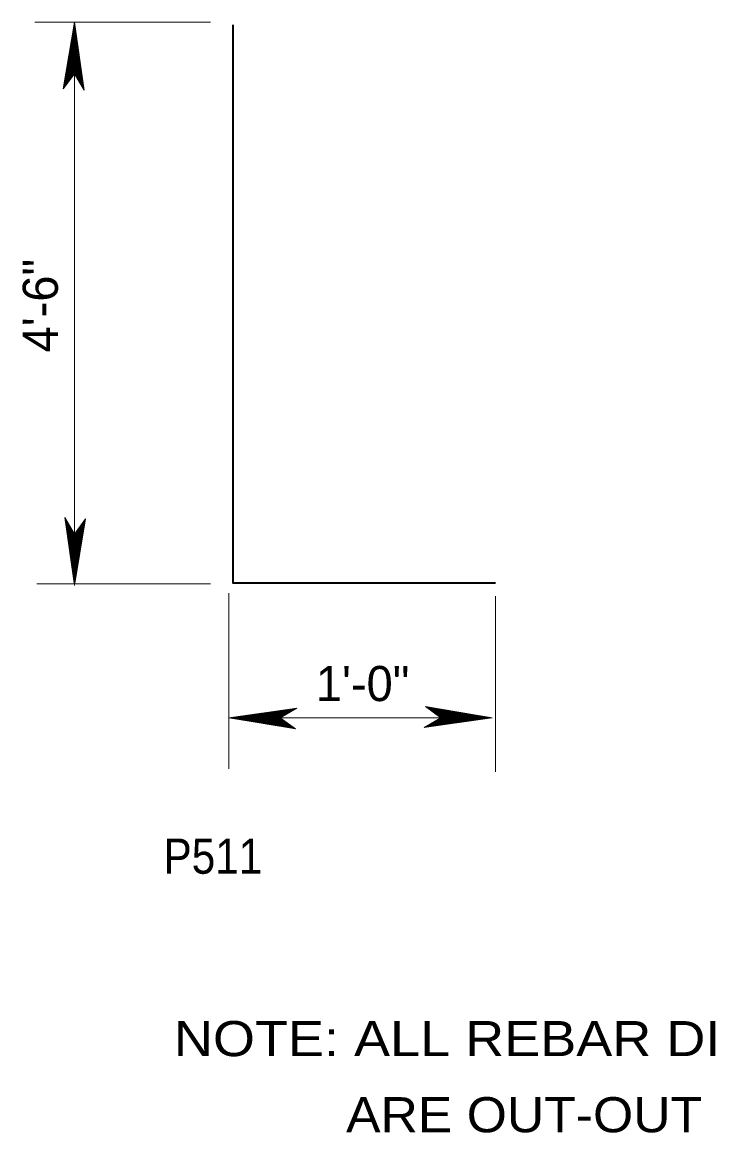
# Model space of a CAD drawing. Extents: x 144 to 252, y 360 to 425.
# Drawn here: x 210.54 to 216.11, y 380.2 to 389.15 of the extents above; entities that cross this region are included whole.
import ezdxf

# ---------------------------------------------------------------- set-up
doc = ezdxf.new("R2010")
doc.units = 0
doc.header["$LTSCALE"] = 0.13
for name, color, linetype, lineweight in [('1', 7, 'Continuous', 40), ('14', 7, 'Continuous', 13), ('3', 7, 'Continuous', 13)]:
    doc.layers.add(name, color=color, linetype=linetype, lineweight=lineweight)

msp = doc.modelspace()

# ---------------------------------------------------------------- linework, layer by layer
at = {"layer": '1', "lineweight": 13}
for p, q in [((212.0607, 389.1547), (210.6441, 389.1547)), ((210.9632, 389.1547), (210.9632, 384.6128)), ((212.0613, 384.625), (210.6616, 384.625)), ((212.2081, 384.5513), (212.2081, 383.1347)), ((214.3577, 384.5267), (214.3577, 383.1101)), ((212.2081, 383.5464), (214.3331, 383.5464))]:
    msp.add_line(p, q, dxfattribs=at)
at = {"layer": '14', "lineweight": 35}
msp.add_lwpolyline([(212.2412, 389.1347), (212.2412, 384.6347), (214.3574, 384.6347)], dxfattribs=at)
at = {"layer": '3'}
for p, q in [((210.9632, 389.1547), (210.874, 388.617)), ((210.9626, 389.1402), (210.8763, 388.6202)), ((210.9626, 389.1294), (210.8787, 388.6235)), ((210.9626, 389.115), (210.8818, 388.6277)), ((210.9626, 389.1022), (210.8845, 388.6315)), ((211.0375, 388.6119), (210.9626, 389.1402)), ((211.0355, 388.6154), (210.9626, 389.1294)), ((211.0328, 388.62), (210.9626, 389.115)), ((211.0304, 388.6241), (210.9626, 389.1022)), ((211.0304, 388.6241), (210.9626, 389.1022)), ((210.9632, 388.7392), (210.9632, 389.1547)), ((211.041, 388.6059), (210.9632, 389.1547)), ((210.9626, 389.0909), (210.8869, 388.6348)), ((210.9626, 389.0765), (210.8901, 388.6391)), ((210.9626, 389.0637), (210.8928, 388.6428)), ((210.9626, 389.05), (210.8957, 388.6469)), ((210.9626, 389.0362), (210.8988, 388.651)), ((210.9626, 389.0229), (210.9016, 388.6549)), ((210.9626, 389.009), (210.9046, 388.659)), ((211.0282, 388.6277), (210.9626, 389.0909)), ((211.0256, 388.6323), (210.9626, 389.0765)), ((211.0232, 388.6364), (210.9626, 389.0637)), ((211.0207, 388.6408), (210.9626, 389.05)), ((211.0181, 388.6452), (210.9626, 389.0362)), ((211.0156, 388.6495), (210.9626, 389.0229)), ((211.0129, 388.654), (210.9626, 389.009)), ((210.9626, 388.9964), (210.9073, 388.6627)), ((210.9626, 388.985), (210.9098, 388.6662)), ((210.9626, 388.9693), (210.9131, 388.6707)), ((210.9626, 388.9555), (210.9161, 388.6748)), ((210.9621, 388.9375), (210.9192, 388.6791)), ((210.9621, 388.9236), (210.9222, 388.6832)), ((210.9988, 388.6783), (210.9621, 388.9375)), ((210.9962, 388.6827), (210.9621, 388.9236)), ((211.0107, 388.658), (210.9626, 388.9964)), ((211.0084, 388.6617), (210.9626, 388.985)), ((211.0056, 388.6667), (210.9626, 388.9693)), ((211.0029, 388.6712), (210.9626, 388.9555)), ((211.0007, 388.6752), (210.9637, 388.9359)), ((210.9621, 388.9104), (210.925, 388.6871)), ((210.9626, 388.9013), (210.9278, 388.6908)), ((210.9626, 388.8893), (210.9303, 388.6944)), ((210.9626, 388.8755), (210.9333, 388.6985)), ((210.9626, 388.8598), (210.9366, 388.7032)), ((210.9626, 388.8472), (210.9393, 388.7068)), ((210.9626, 388.834), (210.9422, 388.7107)), ((210.9937, 388.687), (210.9621, 388.9104)), ((210.9928, 388.6885), (210.9626, 388.9013)), ((210.9906, 388.6924), (210.9626, 388.8893)), ((210.9879, 388.6968), (210.9626, 388.8755)), ((210.9851, 388.7018), (210.9626, 388.8598)), ((210.9827, 388.7059), (210.9626, 388.8472)), ((210.9802, 388.7102), (210.9626, 388.834)), ((210.874, 388.617), (210.9631, 388.7395)), ((210.9626, 388.822), (210.9448, 388.7143)), ((210.9626, 388.8075), (210.9478, 388.7186)), ((210.9626, 388.7937), (210.9508, 388.7227)), ((210.9626, 388.781), (210.9536, 388.7264)), ((210.9626, 388.7677), (210.9564, 388.7303)), ((210.9626, 388.7563), (210.9588, 388.7337)), ((210.9626, 388.7462), (210.9611, 388.7367)), ((210.9779, 388.714), (210.9626, 388.822)), ((210.9752, 388.7187), (210.9626, 388.8075)), ((210.9727, 388.7231), (210.9626, 388.7937)), ((210.9703, 388.7272), (210.9626, 388.781)), ((210.9657, 388.7351), (210.9626, 388.7563)), ((210.9631, 388.7395), (211.041, 388.6059)), ((210.9673, 388.7324), (210.9637, 388.7575)), ((210.8855, 385.1615), (210.9632, 384.6128)), ((210.9634, 385.0279), (210.8855, 385.1615)), ((210.889, 385.1555), (210.9639, 384.6272)), ((210.891, 385.152), (210.9639, 384.638)), ((210.8937, 385.1474), (210.9639, 384.6524)), ((210.8961, 385.1433), (210.9639, 384.6652)), ((210.8961, 385.1433), (210.9639, 384.6652)), ((210.8982, 385.1397), (210.9639, 384.6765)), ((210.9009, 385.1351), (210.9639, 384.6909)), ((210.9033, 385.131), (210.9639, 384.7037)), ((210.9058, 385.1266), (210.9639, 384.7174)), ((210.9084, 385.1222), (210.9639, 384.7312)), ((210.9109, 385.1179), (210.9639, 384.7445)), ((210.9136, 385.1134), (210.9639, 384.7584)), ((210.9158, 385.1094), (210.9639, 384.771)), ((210.9181, 385.1057), (210.9639, 384.7824)), ((210.9209, 385.1007), (210.9639, 384.7981)), ((210.9236, 385.0962), (210.9639, 384.8119)), ((210.9258, 385.0922), (210.9628, 384.8315)), ((210.9278, 385.0891), (210.9644, 384.8299)), ((210.9303, 385.0847), (210.9644, 384.8438)), ((210.9328, 385.0804), (210.9644, 384.857)), ((210.9337, 385.0789), (210.9639, 384.8661)), ((210.9359, 385.075), (210.9639, 384.8781)), ((210.9386, 385.0706), (210.9639, 384.8919)), ((210.9632, 384.6128), (211.0525, 385.1504)), ((211.0525, 385.1504), (210.9634, 385.0279)), ((210.9639, 384.6272), (211.0502, 385.1472)), ((210.9639, 384.638), (211.0478, 385.1439)), ((210.9639, 384.6524), (211.0447, 385.1397)), ((210.9639, 384.6652), (211.042, 385.1359)), ((210.9639, 384.6765), (211.0396, 385.1326)), ((210.9639, 384.6909), (211.0364, 385.1283)), ((210.9639, 384.7037), (211.0337, 385.1246)), ((210.9639, 384.7174), (211.0307, 385.1205)), ((210.9639, 384.7312), (211.0277, 385.1164)), ((210.9639, 384.7445), (211.0249, 385.1125)), ((210.9639, 384.7584), (211.0219, 385.1084)), ((210.9639, 384.771), (211.0192, 385.1047)), ((210.9639, 384.7824), (211.0168, 385.1012)), ((210.9639, 384.7981), (211.0134, 385.0967)), ((210.9639, 384.8119), (211.0104, 385.0926)), ((210.9639, 384.8661), (210.9988, 385.0766)), ((210.9639, 384.8781), (210.9962, 385.073)), ((210.9639, 384.8919), (210.9932, 385.0689)), ((210.9644, 384.8299), (211.0073, 385.0883)), ((210.9644, 384.8438), (211.0043, 385.0842)), ((210.9644, 384.857), (211.0015, 385.0803)), ((210.9414, 385.0656), (210.9639, 384.9076)), ((210.9438, 385.0615), (210.9639, 384.9202)), ((210.9463, 385.0573), (210.9639, 384.9334)), ((210.9486, 385.0534), (210.9639, 384.9454)), ((210.9512, 385.0487), (210.9639, 384.9599)), ((210.9538, 385.0443), (210.9639, 384.9737)), ((210.9562, 385.0403), (210.9639, 384.9864)), ((210.9592, 385.035), (210.9628, 385.0099)), ((210.9608, 385.0323), (210.9639, 385.0111)), ((210.9632, 385.0282), (210.9632, 384.6128)), ((210.9639, 384.9076), (210.9899, 385.0643)), ((210.9639, 384.9202), (210.9872, 385.0606)), ((210.9639, 384.9334), (210.9843, 385.0567)), ((210.9639, 384.9454), (210.9817, 385.0531)), ((210.9639, 384.9599), (210.9787, 385.0488)), ((210.9639, 384.9737), (210.9757, 385.0447)), ((210.9639, 384.9864), (210.9729, 385.041)), ((210.9639, 384.9997), (210.9701, 385.0371)), ((210.9639, 385.0111), (210.9677, 385.0337)), ((210.9639, 385.0213), (210.9654, 385.0307)), ((214.3331, 383.5464), (213.7954, 383.6357)), ((213.7954, 383.6357), (213.9179, 383.5466)), ((214.3331, 383.5464), (213.7954, 383.6357)), ((213.7954, 383.6357), (213.9179, 383.5466)), ((214.3187, 383.5471), (213.7987, 383.6333)), ((214.3187, 383.5471), (213.7987, 383.6333)), ((212.7568, 383.6242), (212.2081, 383.5464)), ((212.2081, 383.5464), (212.7457, 383.4572)), ((212.6235, 383.5464), (212.2081, 383.5464)), ((212.7508, 383.6207), (212.2225, 383.5457)), ((212.2225, 383.5457), (212.7425, 383.4595)), ((212.7473, 383.6187), (212.2333, 383.5457)), ((212.2333, 383.5457), (212.7392, 383.4618)), ((212.7428, 383.616), (212.2477, 383.5457)), ((212.2477, 383.5457), (212.735, 383.465)), ((212.7387, 383.6136), (212.2605, 383.5457)), ((212.7387, 383.6136), (212.2605, 383.5457)), ((212.2605, 383.5457), (212.7312, 383.4677)), ((212.735, 383.6114), (212.2718, 383.5457)), ((212.2718, 383.5457), (212.7279, 383.4701)), ((212.7304, 383.6087), (212.2862, 383.5457)), ((212.2862, 383.5457), (212.7237, 383.4733)), ((212.7263, 383.6063), (212.299, 383.5457)), ((212.299, 383.5457), (212.7199, 383.476)), ((212.7219, 383.6038), (212.3127, 383.5457)), ((212.3127, 383.5457), (212.7158, 383.4789)), ((212.7175, 383.6012), (212.3266, 383.5457)), ((212.3266, 383.5457), (212.7117, 383.4819)), ((212.7132, 383.5987), (212.3398, 383.5457)), ((212.3398, 383.5457), (212.7078, 383.4847)), ((212.7087, 383.5961), (212.3537, 383.5457)), ((212.3537, 383.5457), (212.7037, 383.4878)), ((212.7047, 383.5938), (212.3663, 383.5457)), ((212.3663, 383.5457), (212.7, 383.4904)), ((212.701, 383.5916), (212.3777, 383.5457)), ((212.3777, 383.5457), (212.6966, 383.4929)), ((212.696, 383.5888), (212.3934, 383.5457)), ((212.3934, 383.5457), (212.692, 383.4962)), ((212.6916, 383.5861), (212.4073, 383.5457)), ((212.4073, 383.5457), (212.6879, 383.4992)), ((212.6844, 383.5819), (212.4253, 383.5453)), ((212.4253, 383.5453), (212.6837, 383.5023)), ((212.6876, 383.5838), (212.4268, 383.5468)), ((212.68, 383.5793), (212.4392, 383.5453)), ((212.4392, 383.5453), (212.6795, 383.5053)), ((212.6757, 383.5768), (212.4523, 383.5453)), ((212.4523, 383.5453), (212.6757, 383.5082)), ((212.6743, 383.576), (212.4614, 383.5457)), ((212.4614, 383.5457), (212.6719, 383.5109)), ((212.6703, 383.5737), (212.4734, 383.5457)), ((212.4734, 383.5457), (212.6683, 383.5135)), ((212.6659, 383.5711), (212.4872, 383.5457)), ((212.4872, 383.5457), (212.6642, 383.5165)), ((212.6609, 383.5682), (212.5029, 383.5457)), ((212.5029, 383.5457), (212.6596, 383.5197)), ((212.6568, 383.5658), (212.5155, 383.5457)), ((212.5155, 383.5457), (212.6559, 383.5225)), ((212.6526, 383.5633), (212.5288, 383.5457)), ((212.5288, 383.5457), (212.652, 383.5253)), ((212.6488, 383.5611), (212.5408, 383.5457)), ((212.5408, 383.5457), (212.6484, 383.528)), ((212.6441, 383.5584), (212.5553, 383.5457)), ((212.5553, 383.5457), (212.6442, 383.531)), ((212.6397, 383.5558), (212.5691, 383.5457)), ((212.5691, 383.5457), (212.64, 383.534)), ((212.6356, 383.5535), (212.5817, 383.5457)), ((212.5817, 383.5457), (212.6363, 383.5367)), ((212.595, 383.5457), (212.6324, 383.5396)), ((212.6303, 383.5504), (212.6052, 383.5468)), ((212.6277, 383.5488), (212.6064, 383.5457)), ((212.6064, 383.5457), (212.629, 383.542)), ((212.6166, 383.5457), (212.626, 383.5442)), ((212.6232, 383.5462), (212.7568, 383.6242)), ((212.7457, 383.4572), (212.6232, 383.5462)), ((213.9179, 383.5466), (213.7843, 383.4687)), ((213.9179, 383.5466), (213.7843, 383.4687)), ((213.7843, 383.4687), (214.3331, 383.5464)), ((213.7843, 383.4687), (214.3331, 383.5464)), ((213.7903, 383.4722), (214.3187, 383.5471)), ((213.7903, 383.4722), (214.3187, 383.5471)), ((213.7938, 383.4742), (214.3078, 383.5471)), ((213.7938, 383.4742), (214.3078, 383.5471)), ((213.7984, 383.4768), (214.2934, 383.5471)), ((213.7984, 383.4768), (214.2934, 383.5471)), ((214.3078, 383.5471), (213.8019, 383.631)), ((214.3078, 383.5471), (213.8019, 383.631)), ((213.8025, 383.4792), (214.2807, 383.5471)), ((213.8025, 383.4792), (214.2807, 383.5471)), ((213.8025, 383.4792), (214.2807, 383.5471)), ((213.8025, 383.4792), (214.2807, 383.5471)), ((214.2934, 383.5471), (213.8062, 383.6278)), ((214.2934, 383.5471), (213.8062, 383.6278)), ((213.8062, 383.4814), (214.2693, 383.5471)), ((213.8062, 383.4814), (214.2693, 383.5471)), ((214.2807, 383.5471), (213.8099, 383.6252)), ((214.2807, 383.5471), (213.8099, 383.6252)), ((213.8107, 383.4841), (214.2549, 383.5471)), ((213.8107, 383.4841), (214.2549, 383.5471)), ((214.2693, 383.5471), (213.8132, 383.6227)), ((214.2693, 383.5471), (213.8132, 383.6227)), ((213.8148, 383.4865), (214.2422, 383.5471)), ((213.8148, 383.4865), (214.2422, 383.5471)), ((214.2549, 383.5471), (213.8175, 383.6196)), ((214.2549, 383.5471), (213.8175, 383.6196)), ((213.8192, 383.489), (214.2284, 383.5471)), ((213.8192, 383.489), (214.2284, 383.5471)), ((214.2422, 383.5471), (213.8212, 383.6168)), ((214.2422, 383.5471), (213.8212, 383.6168)), ((213.8237, 383.4916), (214.2146, 383.5471)), ((213.8237, 383.4916), (214.2146, 383.5471)), ((214.2284, 383.5471), (213.8253, 383.6139)), ((214.2284, 383.5471), (213.8253, 383.6139)), ((213.8279, 383.4941), (214.2013, 383.5471)), ((213.8279, 383.4941), (214.2013, 383.5471)), ((214.2146, 383.5471), (213.8294, 383.6109)), ((214.2146, 383.5471), (213.8294, 383.6109)), ((213.8324, 383.4967), (214.1874, 383.5471)), ((213.8324, 383.4967), (214.1874, 383.5471)), ((214.2013, 383.5471), (213.8333, 383.6081)), ((214.2013, 383.5471), (213.8333, 383.6081)), ((213.8364, 383.499), (214.1748, 383.5471)), ((213.8364, 383.499), (214.1748, 383.5471)), ((214.1874, 383.5471), (213.8374, 383.6051)), ((214.1874, 383.5471), (213.8374, 383.6051)), ((213.8402, 383.5012), (214.1634, 383.5471)), ((213.8402, 383.5012), (214.1634, 383.5471)), ((214.1748, 383.5471), (213.8412, 383.6024)), ((214.1748, 383.5471), (213.8412, 383.6024)), ((214.1634, 383.5471), (213.8446, 383.5999)), ((214.1634, 383.5471), (213.8446, 383.5999)), ((213.8452, 383.5041), (214.1478, 383.5471)), ((213.8452, 383.5041), (214.1478, 383.5471)), ((214.1478, 383.5471), (213.8492, 383.5966)), ((214.1478, 383.5471), (213.8492, 383.5966)), ((213.8496, 383.5068), (214.1339, 383.5471)), ((213.8496, 383.5068), (214.1339, 383.5471)), ((214.1339, 383.5471), (213.8533, 383.5936)), ((214.1339, 383.5471), (213.8533, 383.5936)), ((213.8536, 383.509), (214.1143, 383.546)), ((213.8536, 383.509), (214.1143, 383.546)), ((213.8568, 383.5109), (214.1159, 383.5476)), ((213.8568, 383.5109), (214.1159, 383.5476)), ((214.1159, 383.5476), (213.8575, 383.5905)), ((214.1159, 383.5476), (213.8575, 383.5905)), ((213.8612, 383.5135), (214.102, 383.5476)), ((213.8612, 383.5135), (214.102, 383.5476)), ((214.102, 383.5476), (213.8617, 383.5875)), ((214.102, 383.5476), (213.8617, 383.5875)), ((213.8654, 383.516), (214.0888, 383.5476)), ((213.8654, 383.516), (214.0888, 383.5476)), ((214.0888, 383.5476), (213.8655, 383.5847)), ((214.0888, 383.5476), (213.8655, 383.5847)), ((213.8669, 383.5168), (214.0797, 383.5471)), ((213.8669, 383.5168), (214.0797, 383.5471)), ((214.0797, 383.5471), (213.8692, 383.5819)), ((214.0797, 383.5471), (213.8692, 383.5819)), ((213.8708, 383.5191), (214.0677, 383.5471)), ((213.8708, 383.5191), (214.0677, 383.5471)), ((214.0677, 383.5471), (213.8728, 383.5793)), ((214.0677, 383.5471), (213.8728, 383.5793)), ((213.8752, 383.5217), (214.0539, 383.5471)), ((213.8752, 383.5217), (214.0539, 383.5471)), ((214.0539, 383.5471), (213.8769, 383.5763)), ((214.0539, 383.5471), (213.8769, 383.5763)), ((213.8802, 383.5246), (214.0383, 383.5471)), ((213.8802, 383.5246), (214.0383, 383.5471)), ((214.0383, 383.5471), (213.8816, 383.5731)), ((214.0383, 383.5471), (213.8816, 383.5731)), ((213.8843, 383.527), (214.0257, 383.5471)), ((213.8843, 383.527), (214.0257, 383.5471)), ((214.0257, 383.5471), (213.8852, 383.5703)), ((214.0257, 383.5471), (213.8852, 383.5703)), ((213.8886, 383.5295), (214.0124, 383.5471)), ((213.8886, 383.5295), (214.0124, 383.5471)), ((214.0124, 383.5471), (213.8892, 383.5675)), ((214.0124, 383.5471), (213.8892, 383.5675)), ((213.8924, 383.5317), (214.0004, 383.5471)), ((213.8924, 383.5317), (214.0004, 383.5471)), ((214.0004, 383.5471), (213.8928, 383.5648)), ((214.0004, 383.5471), (213.8928, 383.5648)), ((213.9859, 383.5471), (213.897, 383.5618)), ((213.9859, 383.5471), (213.897, 383.5618)), ((213.8971, 383.5344), (213.9859, 383.5471)), ((213.8971, 383.5344), (213.9859, 383.5471)), ((213.9721, 383.5471), (213.9012, 383.5588)), ((213.9721, 383.5471), (213.9012, 383.5588)), ((213.9015, 383.537), (213.9721, 383.5471)), ((213.9015, 383.537), (213.9721, 383.5471)), ((213.9594, 383.5471), (213.9048, 383.5561)), ((213.9594, 383.5471), (213.9048, 383.5561)), ((213.9056, 383.5393), (213.9594, 383.5471)), ((213.9056, 383.5393), (213.9594, 383.5471)), ((213.9462, 383.5471), (213.9087, 383.5532)), ((213.9462, 383.5471), (213.9087, 383.5532)), ((213.9108, 383.5424), (213.9359, 383.546)), ((213.9108, 383.5424), (213.9359, 383.546)), ((213.9347, 383.5471), (213.9122, 383.5508)), ((213.9347, 383.5471), (213.9122, 383.5508)), ((213.9135, 383.544), (213.9347, 383.5471)), ((213.9135, 383.544), (213.9347, 383.5471)), ((213.9246, 383.5471), (213.9152, 383.5486)), ((213.9246, 383.5471), (213.9152, 383.5486)), ((213.9177, 383.5464), (214.3331, 383.5464)), ((213.9177, 383.5464), (214.3331, 383.5464))]:
    msp.add_line(p, q, dxfattribs=at)

# ---------------------------------------------------------------- texts
at = {"layer": '1'}
msp.add_text('4\'-6"', height=0.2833, rotation=90, dxfattribs=at).set_placement((210.8301, 386.4923))
msp.add_text('1\'-0"', height=0.2833, dxfattribs=at).set_placement((212.9103, 383.6805))
for s, width, p in [('P511', 0.9, (211.682, 382.2885)), ('NOTE: ALL REBAR DIMENSIONS', 1.15, (211.7657, 380.8176)), ('ARE OUT-OUT', 1.1, (213.1539, 380.2037))]:
    msp.add_text(s, height=0.2833, dxfattribs=dict(at, width=width)).set_placement(p)

doc.saveas('drawing.dxf')
